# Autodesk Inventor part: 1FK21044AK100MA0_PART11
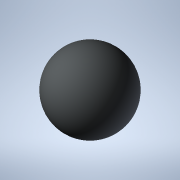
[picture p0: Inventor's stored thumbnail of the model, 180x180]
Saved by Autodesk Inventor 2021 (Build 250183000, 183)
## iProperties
Created: 2025-04
Part Number: 1FK21044AK100MA0_PART11
Material: Generic
Catalog Web Link: www.3dfindit.com
Description: -Servo synchronous motor
Document SubType Name: Modeling
Designer: psAdmin
Mass: 0.137258 g
Surface Area: 1.2868 cm^2
Volume: 0.137258 cm^3
Density: 1 g/cm^3
Appearance: PSOLRGB-212-217-219
Category: PARTsolutions
Title: 1FK21044AK100MA0_PART11
Author: Cadenas PARTsolutions
Comments: Servo synchronous motor
Sending System: PARTsolutions
Preprocessor: ST-DEVELOPER v19.3
PSOL_IDENT_0: {$CADENAS_DATA/23d-libs/siemens_ag/_cat_/5e/d8/1fk21044ak100ma0.prj},216 {VTYP=3D},{NB=1FK21044AK100
PSOL_IDENT_1: MA0_PART11},{LINA=1FK21044AK100MA0_PART11},{NN=1FK21044AK100MA0_PART11},{NOPRJ=TRUE},{DATE=19.08.202
PSOL_IDENT_2: 5 14:00:41},{GEOMDATE=30.07.2025 02:00:53},{VERSION=},{LINEID=10},{WBVAR=},{WBNUMERIC=}  {NB=1FK2104
PSOL_IDENT_3: 4AK100MA0_PART11},{LINA=1FK21044AK100MA0_PART11},{KT=DUMMY},{PREVIEW=../../../_pool_/cb/72/p_d211_xx
PSOL_IDENT_4: _00434j.png},{DESCSHORT=SIMOTICS S-1FK2 HD, SINAMICS S210 3AC 400V-480V, 0.95 Nm, 6000 rpm},{DESCLON
PSOL_IDENT_5: G=SIMOTICS S-1FK2 HD servo motor M0=1.27 Nm; PN = 0.6 kW at nN=6000 rpm (380-480 V); PN = 0.4 kW at
PSOL_IDENT_6: nN=3000 rpm (200-240 V); with holding brake; degree of protection IP64; cylindrical shaft D19x40mm;
PSOL_IDENT_7: absolute encoder 22-bit + 12-bit multiturn (encoder AM22DQC); with OCC interface; plug size M17, rot
PSOL_IDENT_8: atable; SIMOTICS S-1FK2 servomotorfor a wide range of uses in industrial environments. SIMOTICS S‑1F
PSOL_IDENT_9: K2 servomotors are compact synchronous motors with a high dynamic performance that set themselves ap
PSOL_IDENT_10: art as a result of their high power density, degree of protection and overload capability. The motor
PSOL_IDENT_11: s are available in two variants: as High Dynamic variant (highest dynamic performance as a result of
PSOL_IDENT_12: the low intrinsic moment of inertia for applications demanding a high dynamic performance with low
PSOL_IDENT_13: moved masses) - and as Compact variant (precise and stable closed-loop control for medium up to larg
PSOL_IDENT_14: e moved masses as a result of a medium intrinsic moment of inertia). SIMOTICSS‑1FK2 servomotors full
PSOL_IDENT_15: y exploit their strengths in a system with the SINAMICSS210 frequency converter and simple connectio
PSOL_IDENT_16: n using the one cable connection (OCC). Advantages include the short control and positioning times,
PSOL_IDENT_17: fast and precise correction of disturbing quantities as well as stable control with a high dynamic p
PSOL_IDENT_18: erformance. The servo motors can be configured to address a wide range of requirements. For example
PSOL_IDENT_19: with and without holding brake, IP64 or IP65 degree of protection, singleturn or multiturn absolute
PSOL_IDENT_20: encoders - to name just a few. Further, the servomotors are available in different shaft heights ext
PSOL_IDENT_21: ending from 20 to 100. A shaft sealing ring is available to achieve an IP65 degree of protection and
PSOL_IDENT_22: for subsequent mounting at the motor or as spare part. SIMOTICS - the optimum motor for each and ev
PSOL_IDENT_23: ery motion control application.},{INTNO=804766910005},{SUPPLIERALTNO=1FK2104-4AK10-0MA0},{MANUID=1FK
PSOL_IDENT_24: 21044AK100MA0},{MANUNAME=Siemens},{MANUTYPEDESC=Synchronous motor 1FK2-HD 1,27 Nm},{AAU732=SIMOTICS}
PSOL_IDENT_25: ,{AAO057=S-1FK2},{AAU734=SIMOTICS S-1FK2 HD servo motor M0=1.27 Nm; PN = 0.6 kW at nN=6000 rpm (380-
PSOL_IDENT_26: 480 V); PN = 0.4 kW at nN=3000 rpm (200-240 V); with holding brake; degree of protection IP64; cylin
PSOL_IDENT_27: drical shaft D19x40mm; absolute encoder 22-bit + 12-bit multiturn (encoder AM22DQC); with OCC interf
PSOL_IDENT_28: ace; plug size M17, rotatable;},{AAW338=Synchronous motor 1FK2-HD 1,27 Nm},{AAO742=SIMOTICS},{AAO663=
PSOL_IDENT_29: 4042948691076},{NOCUPEROU=1},{PRICEQUANTITY=1},{QUANTITYMIN=1},{QUANTITYINT=1},{CTN=85015100},{COO=D
PSOL_IDENT_30: E},{AAO676=1FK2104-4AK10-0MA0},{AAO677=Siemens AG},{ORDERUNIT=C62},{CONTENTUNIT=C62}
NB: 1FK21044AK100MA0_PART11
NT: Servo synchronous motor
NBSYN: $MANUID._PART11
LINA: 1FK21044AK100MA0_PART11
CATALOG: SIEMENS
PREVIEW: ../../../_pool_/cb/72/p_d211_xx_00434j.png
DESCSHORT: SIMOTICS S-1FK2 HD, SINAMICS S210 3AC 400V-480V, 0.95 Nm, 6000 rpm
DESCLONG: SIMOTICS S-1FK2 HD servo motor M0=1.27 Nm; PN = 0.6 kW at nN=6000 rpm (380-480 V); PN = 0.4 kW at nN=3000 rpm (200-240 V); with holding brake; degree of protect
INTNO: 804766910005
SUPPLIERALTNO: 1FK2104-4AK10-0MA0
MANUID: 1FK21044AK100MA0
MANUNAME: Siemens
MANUTYPEDESC: Synchronous motor 1FK2-HD 1,27 Nm
AAU732: SIMOTICS
AAO057: S-1FK2
AAU734: SIMOTICS S-1FK2 HD servo motor M0=1.27 Nm; PN = 0.6 kW at nN=6000 rpm (380-480 V); PN = 0.4 kW at nN=3000 rpm (200-240 V); with holding brake; degree of protect
AAW338: Synchronous motor 1FK2-HD 1,27 Nm
AAO742: SIMOTICS
AAO663: 4042948691076.0
NOCUPEROU: 1
PRICEQUANTITY: 1
QUANTITYMIN: 1
QUANTITYINT: 1
CTN: 85015100
COO: DE
ARTICLENO: 1FK21044AK100MA0_PART11
BOMINFO: 1FK21044AK100MA0_PART11
CREATOR: CADENAS GmbH
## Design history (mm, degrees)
feature "2025_04_17_15_35_41_0968"
body "Solid1"
